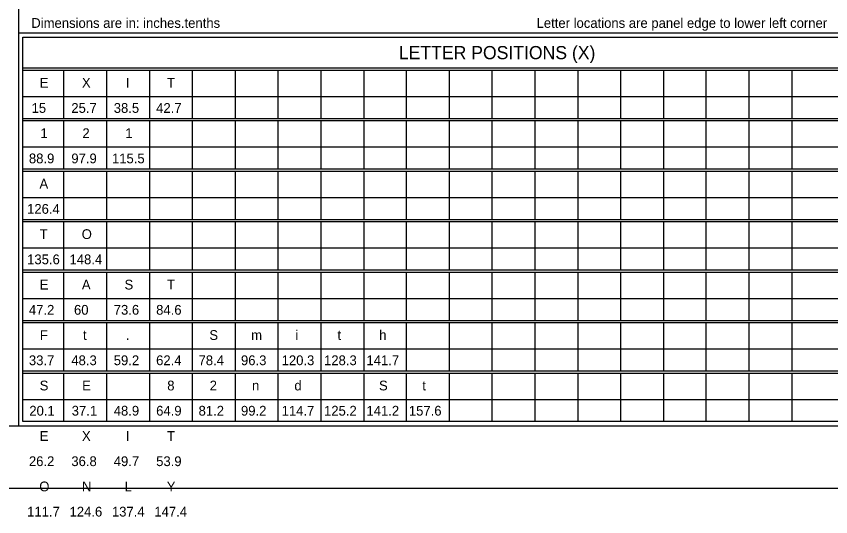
# Model space of a CAD drawing. Extents: x 2149934 to 2150188, y 145113 to 145238.
# Drawn here: x 2150076.2 to 2150119.25, y 145112.59 to 145139.02 of the extents above; entities that cross this region are included whole.
import ezdxf

# ---------------------------------------------------------------- set-up
doc = ezdxf.new("R2010")
doc.units = 0
for name, color, linetype in [('BORDER', 7, 'Continuous'), ('Level 1', 7, 'Continuous'), ('PDF', 7, 'Continuous')]:
    doc.layers.add(name, color=color, linetype=linetype)

msp = doc.modelspace()

# ---------------------------------------------------------------- linework, layer by layer
at = {"layer": 'BORDER'}
for p, q in [((2150017.557, 145117.388), (2150171.536, 145117.388)), ((2150010.458, 145114.088), (2150174.061, 145114.088))]:
    msp.add_line(p, q, dxfattribs=at)
at = {"layer": 'Level 1'}
for p, q in [((2150076.316, 145216.512), (2150076.316, 145117.388)), ((2150076.316, 145138.143), (2150121.342, 145138.143)), ((2150076.548, 145136.288), (2150134.843, 145136.288)), ((2150076.548, 145136.172), (2150134.843, 145136.172)), ((2150078.704, 145136.172), (2150078.704, 145133.621)), ((2150080.977, 145136.172), (2150080.977, 145133.621)), ((2150083.25, 145136.172), (2150083.25, 145133.621)), ((2150085.499, 145136.172), (2150085.499, 145133.621)), ((2150087.772, 145136.172), (2150087.772, 145133.621)), ((2150090.021, 145136.172), (2150090.021, 145133.621)), ((2150092.294, 145136.172), (2150092.294, 145133.621)), ((2150094.566, 145136.172), (2150094.566, 145133.621)), ((2150096.816, 145136.172), (2150096.816, 145133.621)), ((2150099.088, 145136.172), (2150099.088, 145133.621)), ((2150101.337, 145136.172), (2150101.337, 145133.621)), ((2150103.61, 145136.172), (2150103.61, 145133.621)), ((2150105.883, 145136.172), (2150105.883, 145133.621)), ((2150108.132, 145136.172), (2150108.132, 145133.621)), ((2150110.405, 145136.172), (2150110.405, 145133.621)), ((2150112.654, 145136.172), (2150112.654, 145133.621)), ((2150114.927, 145136.172), (2150114.927, 145133.621)), ((2150117.199, 145136.172), (2150117.199, 145133.621)), ((2150076.548, 145134.78), (2150126.185, 145134.78)), ((2150076.548, 145133.621), (2150134.843, 145133.621)), ((2150076.548, 145133.505), (2150134.843, 145133.505)), ((2150078.704, 145133.505), (2150078.704, 145130.954)), ((2150080.977, 145133.505), (2150080.977, 145130.954)), ((2150083.25, 145133.505), (2150083.25, 145130.954)), ((2150085.499, 145133.505), (2150085.499, 145130.954)), ((2150087.772, 145133.505), (2150087.772, 145130.954)), ((2150090.021, 145133.505), (2150090.021, 145130.954)), ((2150092.294, 145133.505), (2150092.294, 145130.954)), ((2150094.566, 145133.505), (2150094.566, 145130.954)), ((2150096.816, 145133.505), (2150096.816, 145130.954)), ((2150099.088, 145133.505), (2150099.088, 145130.954)), ((2150101.337, 145133.505), (2150101.337, 145130.954)), ((2150103.61, 145133.505), (2150103.61, 145130.954)), ((2150105.883, 145133.505), (2150105.883, 145130.954)), ((2150108.132, 145133.505), (2150108.132, 145130.954)), ((2150110.405, 145133.505), (2150110.405, 145130.954)), ((2150112.654, 145133.505), (2150112.654, 145130.954)), ((2150114.927, 145133.505), (2150114.927, 145130.954)), ((2150117.199, 145133.505), (2150117.199, 145130.954)), ((2150076.548, 145132.113), (2150126.185, 145132.113)), ((2150076.548, 145130.954), (2150134.843, 145130.954)), ((2150076.548, 145130.838), (2150134.843, 145130.838)), ((2150078.704, 145130.838), (2150078.704, 145128.287)), ((2150080.977, 145130.838), (2150080.977, 145128.287)), ((2150083.25, 145130.838), (2150083.25, 145128.287)), ((2150085.499, 145130.838), (2150085.499, 145128.287)), ((2150087.772, 145130.838), (2150087.772, 145128.287)), ((2150090.021, 145130.838), (2150090.021, 145128.287)), ((2150092.294, 145130.838), (2150092.294, 145128.287)), ((2150094.566, 145130.838), (2150094.566, 145128.287)), ((2150096.816, 145130.838), (2150096.816, 145128.287)), ((2150099.088, 145130.838), (2150099.088, 145128.287)), ((2150101.337, 145130.838), (2150101.337, 145128.287)), ((2150103.61, 145130.838), (2150103.61, 145128.287)), ((2150105.883, 145130.838), (2150105.883, 145128.287)), ((2150108.132, 145130.838), (2150108.132, 145128.287)), ((2150110.405, 145130.838), (2150110.405, 145128.287)), ((2150112.654, 145130.838), (2150112.654, 145128.287)), ((2150114.927, 145130.838), (2150114.927, 145128.287)), ((2150117.199, 145130.838), (2150117.199, 145128.287)), ((2150076.548, 145129.447), (2150126.185, 145129.447)), ((2150076.548, 145128.287), (2150134.843, 145128.287)), ((2150076.548, 145128.171), (2150134.843, 145128.171)), ((2150078.704, 145128.171), (2150078.704, 145125.62)), ((2150080.977, 145128.171), (2150080.977, 145125.62)), ((2150083.25, 145128.171), (2150083.25, 145125.62)), ((2150085.499, 145128.171), (2150085.499, 145125.62)), ((2150087.772, 145128.171), (2150087.772, 145125.62)), ((2150090.021, 145128.171), (2150090.021, 145125.62)), ((2150092.294, 145128.171), (2150092.294, 145125.62)), ((2150094.566, 145128.171), (2150094.566, 145125.62)), ((2150096.816, 145128.171), (2150096.816, 145125.62)), ((2150099.088, 145128.171), (2150099.088, 145125.62)), ((2150101.337, 145128.171), (2150101.337, 145125.62)), ((2150103.61, 145128.171), (2150103.61, 145125.62)), ((2150105.883, 145128.171), (2150105.883, 145125.62)), ((2150108.132, 145128.171), (2150108.132, 145125.62)), ((2150110.405, 145128.171), (2150110.405, 145125.62)), ((2150112.654, 145128.171), (2150112.654, 145125.62)), ((2150114.927, 145128.171), (2150114.927, 145125.62)), ((2150117.199, 145128.171), (2150117.199, 145125.62)), ((2150076.548, 145126.78), (2150126.185, 145126.78)), ((2150076.548, 145125.62), (2150134.843, 145125.62)), ((2150076.548, 145125.504), (2150134.843, 145125.504)), ((2150078.704, 145125.504), (2150078.704, 145122.954)), ((2150080.977, 145125.504), (2150080.977, 145122.954)), ((2150083.25, 145125.504), (2150083.25, 145122.954)), ((2150085.499, 145125.504), (2150085.499, 145122.954)), ((2150087.772, 145125.504), (2150087.772, 145122.954)), ((2150090.021, 145125.504), (2150090.021, 145122.954)), ((2150092.294, 145125.504), (2150092.294, 145122.954)), ((2150094.566, 145125.504), (2150094.566, 145122.954)), ((2150096.816, 145125.504), (2150096.816, 145122.954)), ((2150099.088, 145125.504), (2150099.088, 145122.954)), ((2150101.337, 145125.504), (2150101.337, 145122.954)), ((2150103.61, 145125.504), (2150103.61, 145122.954)), ((2150105.883, 145125.504), (2150105.883, 145122.954)), ((2150108.132, 145125.504), (2150108.132, 145122.954)), ((2150110.405, 145125.504), (2150110.405, 145122.954)), ((2150112.654, 145125.504), (2150112.654, 145122.954)), ((2150114.927, 145125.504), (2150114.927, 145122.954)), ((2150117.199, 145125.504), (2150117.199, 145122.954)), ((2150076.548, 145124.113), (2150126.185, 145124.113)), ((2150076.548, 145122.954), (2150134.843, 145122.954)), ((2150076.548, 145122.838), (2150134.843, 145122.838)), ((2150078.704, 145122.838), (2150078.704, 145120.287)), ((2150080.977, 145122.838), (2150080.977, 145120.287)), ((2150083.25, 145122.838), (2150083.25, 145120.287)), ((2150085.499, 145122.838), (2150085.499, 145120.287)), ((2150087.772, 145122.838), (2150087.772, 145120.287)), ((2150090.021, 145122.838), (2150090.021, 145120.287)), ((2150092.294, 145122.838), (2150092.294, 145120.287)), ((2150094.566, 145122.838), (2150094.566, 145120.287)), ((2150096.816, 145122.838), (2150096.816, 145120.287)), ((2150099.088, 145122.838), (2150099.088, 145120.287)), ((2150101.337, 145122.838), (2150101.337, 145120.287)), ((2150103.61, 145122.838), (2150103.61, 145120.287)), ((2150105.883, 145122.838), (2150105.883, 145120.287)), ((2150108.132, 145122.838), (2150108.132, 145120.287)), ((2150110.405, 145122.838), (2150110.405, 145120.287)), ((2150112.654, 145122.838), (2150112.654, 145120.287)), ((2150114.927, 145122.838), (2150114.927, 145120.287)), ((2150117.199, 145122.838), (2150117.199, 145120.287)), ((2150076.548, 145121.446), (2150126.185, 145121.446)), ((2150076.548, 145120.287), (2150134.843, 145120.287)), ((2150076.548, 145120.171), (2150134.843, 145120.171)), ((2150078.704, 145120.171), (2150078.704, 145117.62)), ((2150080.977, 145120.171), (2150080.977, 145117.62)), ((2150083.25, 145120.171), (2150083.25, 145117.62)), ((2150085.499, 145120.171), (2150085.499, 145117.62)), ((2150087.772, 145120.171), (2150087.772, 145117.62)), ((2150090.021, 145120.171), (2150090.021, 145117.62)), ((2150092.294, 145120.171), (2150092.294, 145117.62)), ((2150094.566, 145120.171), (2150094.566, 145117.62)), ((2150096.816, 145120.171), (2150096.816, 145117.62)), ((2150099.088, 145120.171), (2150099.088, 145117.62)), ((2150101.337, 145120.171), (2150101.337, 145117.62)), ((2150103.61, 145120.171), (2150103.61, 145117.62)), ((2150105.883, 145120.171), (2150105.883, 145117.62)), ((2150108.132, 145120.171), (2150108.132, 145117.62)), ((2150110.405, 145120.171), (2150110.405, 145117.62)), ((2150112.654, 145120.171), (2150112.654, 145117.62)), ((2150114.927, 145120.171), (2150114.927, 145117.62)), ((2150117.199, 145120.171), (2150117.199, 145117.62)), ((2150076.548, 145118.779), (2150126.185, 145118.779))]:
    msp.add_line(p, q, dxfattribs=at)
msp.add_lwpolyline([(2150076.548, 145137.911), (2150134.843, 145137.911), (2150134.843, 145117.62), (2150076.548, 145117.62)], close=True, dxfattribs=at)
at = {"layer": 'PDF'}
msp.add_lwpolyline([(2150010.458, 145114.088), (2150174.061, 145114.088), (2150174.061, 145219.948), (2150010.458, 145219.948)], close=True, dxfattribs=at)

# ---------------------------------------------------------------- texts
at = {"layer": 'Level 1'}
for s, height, p in [('Dimensions are in: inches.tenths', 0.51652, (2150076.993, 145138.406)), ('Letter locations are panel edge to lower left corner', 0.51652, (2150103.701, 145138.406)), ('LETTER POSITIONS (X)', 0.69555, (2150096.422, 145136.751)), ('E', 0.517, (2150077.437, 145135.248)), ('X', 0.517, (2150079.67, 145135.248)), ('I', 0.517, (2150081.989, 145135.248)), ('T', 0.517, (2150084.167, 145135.248)), ('15', 0.5165, (2150077.008, 145133.916)), ('25.7', 0.5165, (2150079.109, 145133.916)), ('38.5', 0.5165, (2150081.351, 145133.916)), ('42.7', 0.5165, (2150083.593, 145133.916)), ('1', 0.517, (2150077.474, 145132.583)), ('2', 0.517, (2150079.695, 145132.583)), ('1', 0.517, (2150081.958, 145132.583)), ('88.9', 0.5165, (2150076.867, 145131.251)), ('97.9', 0.5165, (2150079.109, 145131.251)), ('115.5', 0.5165, (2150081.257, 145131.251)), ('A', 0.517, (2150077.425, 145129.917)), ('126.4', 0.5165, (2150076.771, 145128.585)), ('T', 0.517, (2150077.441, 145127.252)), ('O', 0.517, (2150079.658, 145127.252)), ('135.6', 0.5165, (2150076.773, 145125.92)), ('148.4', 0.5165, (2150079.013, 145125.92)), ('E', 0.517, (2150077.437, 145124.586)), ('A', 0.517, (2150079.667, 145124.587)), ('S', 0.517, (2150081.921, 145124.587)), ('T', 0.517, (2150084.167, 145124.587)), ('47.2', 0.5165, (2150076.867, 145123.254)), ('60', 0.5165, (2150079.25, 145123.254)), ('73.6', 0.5165, (2150081.351, 145123.254)), ('84.6', 0.5165, (2150083.593, 145123.254)), ('F', 0.517, (2150077.446, 145121.921)), ('t', 0.517, (2150079.726, 145121.921)), ('S', 0.517, (2150086.405, 145121.921)), ('m', 0.517, (2150088.614, 145121.921)), ('i', 0.517, (2150090.957, 145121.921)), ('t', 0.517, (2150093.177, 145121.921)), ('h', 0.517, (2150095.384, 145121.921)), ('.', 0.517, (2150081.989, 145121.921)), ('33.7', 0.5165, (2150076.867, 145120.589)), ('48.3', 0.5165, (2150079.109, 145120.589)), ('59.2', 0.5165, (2150081.351, 145120.589)), ('62.4', 0.5165, (2150083.591, 145120.589)), ('78.4', 0.5165, (2150085.833, 145120.589)), ('96.3', 0.5165, (2150088.077, 145120.589)), ('120.3', 0.5165, (2150090.225, 145120.589)), ('128.3', 0.5165, (2150092.467, 145120.589)), ('141.7', 0.5165, (2150094.709, 145120.589)), ('S', 0.517, (2150077.437, 145119.256)), ('E', 0.517, (2150079.679, 145119.256)), ('8', 0.517, (2150084.179, 145119.256)), ('2', 0.517, (2150086.421, 145119.256)), ('n', 0.517, (2150088.658, 145119.256)), ('d', 0.517, (2150090.9, 145119.256)), ('S', 0.517, (2150095.372, 145119.256)), ('t', 0.517, (2150097.661, 145119.256)), ('20.1', 0.5165, (2150076.888, 145117.924)), ('37.1', 0.5165, (2150079.13, 145117.924)), ('48.9', 0.5165, (2150081.351, 145117.924)), ('64.9', 0.5165, (2150083.593, 145117.924)), ('81.2', 0.5165, (2150085.835, 145117.924)), ('99.2', 0.5165, (2150088.077, 145117.924)), ('114.7', 0.5165, (2150090.225, 145117.924)), ('125.2', 0.5165, (2150092.467, 145117.924)), ('141.2', 0.5165, (2150094.709, 145117.924)), ('157.6', 0.5165, (2150096.951, 145117.924)), ('E', 0.517, (2150077.437, 145116.59)), ('X', 0.517, (2150079.671, 145116.59)), ('I', 0.517, (2150081.989, 145116.59)), ('T', 0.517, (2150084.167, 145116.59)), ('26.2', 0.5165, (2150076.867, 145115.258)), ('36.8', 0.5165, (2150079.109, 145115.258)), ('49.7', 0.5165, (2150081.351, 145115.258)), ('53.9', 0.5165, (2150083.593, 145115.258)), ('O', 0.517, (2150077.416, 145113.925)), ('N', 0.517, (2150079.672, 145113.925)), ('L', 0.517, (2150081.925, 145113.925)), ('Y', 0.517, (2150084.154, 145113.925)), ('111.7', 0.5165, (2150076.773, 145112.593)), ('124.6', 0.5165, (2150079.015, 145112.593)), ('137.4', 0.5165, (2150081.255, 145112.593)), ('147.4', 0.5165, (2150083.497, 145112.593))]:
    msp.add_text(s, height=height, dxfattribs=at).set_placement(p)

doc.saveas('drawing.dxf')
